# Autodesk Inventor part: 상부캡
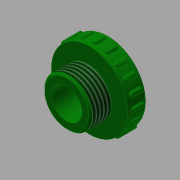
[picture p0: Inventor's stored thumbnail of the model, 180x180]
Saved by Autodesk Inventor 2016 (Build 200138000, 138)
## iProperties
Created: 2015-12
Part Number: 상부캡
Material: PC/ABS 플라스틱
Document SubType Name: Modeling
Designer: mduedu
Density: 7.86 g/cm^3
Appearance: 진녹색
Author: mduedu
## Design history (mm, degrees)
sketch "스케치1"
  geometry: C1 r 12.5 at (0, 0); C2 r 8 at (0, 0); 1 further point
  constraints: 2 centre point, 2 coincident
  dimensions: "d1" = 25 diameter of C1; "d3" = 16 diameter of C2
extrude "돌출1" new body sketch "스케치1" distance "d4" = 12; taper "d6" = 0 deg; dims "d5" = 12, "d7" = 0
sketch "스케치2"
  geometry: C1 r 20 at (0, 0); C2 r 12.5 at (0, 0) reference; 1 further point
  constraints: 1 centre point, 1 coincident
  dimensions: "d8" = 40 diameter of C1
extrude "돌출2" join sketch "스케치2" distance "d10" = 10; taper "d11" = 0 deg
extrude "돌출3" cut sketch "스케치1" stored distance "d34" = 10; taper "d35" = 0 deg
sketch "스케치5"
  geometry: L1 (-20, 0)-(-20, 10) reference; L2 (-20, 10)-(-12.5, 10) reference; L3 (-12.5, 10)-(-12.5, 12) reference; L4 (-12.5, 12)-(12.5, 12) reference; L5 (12.5, 12)-(12.5, 10) reference; L6 (12.5, 10)-(20, 10) reference; L7 (20, 10)-(20, 0) reference; L8 (20, 0)-(12.5, 0) reference; L9 (12.5, 0)-(12.5, -12) reference; L10 (12.5, -12)-(8, -12) reference; L11 (8, -12)-(8, 0) reference; L12 (8, 0)-(-8, 0) reference; L13 (-8, 0)-(-8, -12) reference; L14 (-8, -12)-(-12.5, -12) reference; L15 (-12.5, -12)-(-12.5, 0) reference; L16 (-12.5, 0)-(-20, 0) reference; L17 (12.5, 0)-(10.5, 0); L18 (10.5, 0)-(10.5, -1); L19 (10.5, -1)-(12.5, -1); L20 (12.5, -1)-(12.5, 0); 2 further points
  constraints: 8 end point, 2 parallel, 1 horizontal, 1 midpoint, 1 perpendicular, 1 vertical alignment, 2 other
  dimensions: "d36" = 2 distance of L19.end L18.end; "d37" = 1 distance of L18.end L17.end
revolve "회전1" sketch "스케치5" stored, may be unused: angle "d38" = 90 deg
feature "스레드1" dims "d39" = 10, "d40" = 0
chamfer "모따기3" distance "d41" = 1; stored, may be unused: second distance "d42" = 2, angle "d43" = 45 deg
fillet "모깎기4" dims "d44" = 3
node "작업 평면1"
sketch "스케치7"
  geometry: L1 (1, 0)-(-1, 0); L2 (-1, 0)-(-1, 20.976); L3 (1, 20.976)-(1, 0); C1 r 20 at (0, 0) reference; A1 r 21 centre (0, 0) between (1, 20.976) and (-1, 20.976); 2 further points
  constraints: 6 end point, 2 coincident, 2 point on circle, 1 centre point, 1 horizontal, 1 midpoint, 1 parallel, 1 perpendicular
  dimensions: "d48" = 2 distance of L1.start L1.end; "d49" = 1 radial gap between concentric circles of A1 C1
extrude "돌출4" join sketch "스케치7" distance "d50" = 3; taper "d52" = 0 deg; dims "d51" = 3, "d53" = 0
fillet "모깎기5" dims "d54" = 1
fillet "모깎기6" dims "d55" = 0.5
fillet "모깎기7" dims "d59" = 1
sketch "스케치8"
  geometry: 2 further points
  constraints: 1 coincident, 1 other
feature "엠보싱1" sketch "스케치8" dims "d60" = 0.5, "d61" = 0
node "솔리드1"
pattern_circular "원형 패턴1" dims "d57" = 360 deg
node "절단 모서리 투영1"
node "절단 모서리 투영3"
